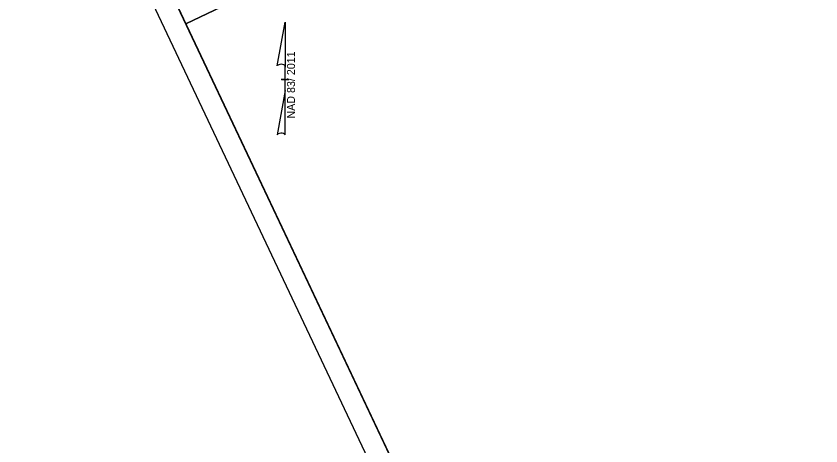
# Model space of a CAD drawing. Extents: x 476855 to 478565, y 498324 to 500313.
# Drawn here: x 476855 to 477710, y 499068 to 499525 of the extents above; entities that cross this region are included whole.
import ezdxf

# ---------------------------------------------------------------- set-up
doc = ezdxf.new("R2010")
doc.units = 0
for name, color, linetype in [('Prop Grid Mask', 7, 'Continuous'), ('Prop North Arrow NAD83 for Plan Sheets CELL', 7, 'Continuous'), ('Sheet Layout Plan Border', 7, 'Continuous'), ('Sheet Plan CELL', 7, 'Continuous'), ('Sheet Plot Border Outside CELL', 7, 'Continuous')]:
    doc.layers.add(name, color=color, linetype=linetype)

msp = doc.modelspace()

# ---------------------------------------------------------------- linework, layer by layer
at = {"layer": 'Prop Grid Mask'}
msp.add_lwpolyline([(476968.39, 499659.01), (477035.62, 499516.73), (477073.33, 499534.55), (477006.1, 499676.83)], close=True, dxfattribs=at)
at = {"layer": 'Prop North Arrow NAD83 for Plan Sheets CELL'}
for p, q in [((477132.72, 499472.09), (477140.92, 499518.44)), ((477140.97, 499518.44), (477140.92, 499518.44)), ((477140.97, 499518.44), (477140.92, 499518.44)), ((477140.97, 499518.44), (477140.97, 499470.64)), ((477140.97, 499445.84), (477140.97, 499472.04)), ((477140.97, 499470.64), (477140.97, 499471.99)), ((477136.97, 499457.44), (477136.92, 499457.44)), ((477140.52, 499457.44), (477136.97, 499457.44)), ((477137.02, 499457.44), (477145.02, 499457.44)), ((477140.97, 499445.84), (477132.62, 499398.59)), ((477141.02, 499398.79), (477140.97, 499445.84))]:
    msp.add_line(p, q, dxfattribs=at)
for centre, start_param, end_param in [((477136.86, 499471.6), 0.216388, 2.908219), ((477136.86, 499398.43), 0.201328, 3.141593)]:
    msp.add_ellipse(centre, major_axis=(4.23, -0.03), ratio=0.461098, start_param=start_param, end_param=end_param, dxfattribs=at)
at = {"layer": 'Sheet Layout Plan Border'}
msp.add_lwpolyline([(478473.37, 498931.82), (477903.68, 500137.33), (477832.75, 500100.13), (477759.99, 500254.29), (477648.51, 500201.67), (477648.51, 500201.67), (477181.74, 499981.09), (477039.82, 499914.02), (477125.29, 499733.16), (477006.1, 499676.83), (477073.33, 499534.55), (477035.61, 499516.73), (477523.84, 498483.65)], close=True, dxfattribs=at)
at = {"layer": 'Sheet Plan CELL'}
for points in [[(476882.9, 499839.89), (477523.8, 498483.67), (478473.14, 498932.29), (477832.24, 500288.49)], [(478473.17, 498932.3), (477523.84, 498483.65), (476968.37, 499659.01), (477104.04, 499723.12), (477018.58, 499903.99), (477832.24, 500288.49)]]:
    msp.add_lwpolyline(points, close=True, dxfattribs=at)
at = {"layer": 'Sheet Plot Border Outside CELL'}
msp.add_lwpolyline([(477845.33, 500313.48), (478564.63, 498791.38), (477574.61, 498323.53), (476855.31, 499845.63)], close=True, dxfattribs=at)

# ---------------------------------------------------------------- texts
at = {"layer": 'Prop North Arrow NAD83 for Plan Sheets CELL'}
msp.add_text('NAD 83/ 2011', height=8.5, rotation=90, dxfattribs=at).set_placement((477151.49, 499415.93))

doc.saveas('drawing.dxf')
